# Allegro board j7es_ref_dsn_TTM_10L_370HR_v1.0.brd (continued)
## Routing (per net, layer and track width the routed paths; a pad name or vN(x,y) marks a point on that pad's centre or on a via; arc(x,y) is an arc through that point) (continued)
C_SGMII2_TX0_N: length 50.7
  TOP w0.122: U9.AF18 v1(95.85,80.95)
  L7-SIGNAL w0.099: v1(89.28,126.99) 89.48,126.79 arc(89.53,126.72) 89.56,126.63 arc(89.56,126.61) 89.56,126.59 89.56,126.14 arc(89.61,125.89) 89.75,125.69 92.36,123.07 arc(92.66,122.87) 93.02,122.8 93.05,122.8 arc(93.18,122.77) 93.29,122.7 93.48,122.51 arc(93.66,122.24) 93.73,121.92 93.73,118.68 arc(93.81,118.26) 94.05,117.9 94.85,117.09 arc(95.15,116.66) 95.25,116.14 95.25,100.87 arc(95.41,100.05) 95.88,99.35 96.33,98.9 arc(96.68,98.38) 96.8,97.77 96.8,84.36 arc(96.77,84.28) 96.72,84.22 96.69,84.18 96.68,84.18 arc(96.56,84.03) 96.52,83.84 arc(96.5,83.75) 96.45,83.67 96.34,83.56 arc(96.27,83.45) 96.24,83.31 96.24,81.68 arc(96.18,81.37) 96,81.1 v1(95.85,80.95)
  BOTTOM w0.188: C215.1 89.33,127.68 89.33,127.04 v1(89.28,126.99)
C_SGMII2_TX0_P: length 50.7
  TOP w0.122: U9.AG17 v1(96.65,81.75)
  L7-SIGNAL w0.099: v1(96.65,81.75) 96.65,81.5 arc(96.74,81.37) 96.9,81.4 96.96,81.45 arc(97.01,81.53) 97.03,81.63 97.03,83.4 97.02,83.41 arc(96.99,83.53) 96.92,83.64 96.9,83.66 arc(96.83,83.82) 96.9,83.98 96.9,83.99 arc(97.01,84.16) 97.05,84.36 97.05,97.77 arc(96.91,98.48) 96.51,99.08 96.06,99.53 arc(95.65,100.14) 95.5,100.87 95.5,100.87 95.5,116.14 arc(95.38,116.75) 95.03,117.27 94.23,118.08 arc(94.05,118.36) 93.98,118.68 93.98,121.92 arc(93.9,122.33) 93.66,122.69 93.47,122.88 arc(93.28,123.01) 93.05,123.05 93.02,123.05 arc(92.76,123.1) 92.54,123.25 89.93,125.87 arc(89.84,125.99) 89.81,126.14 89.81,126.64 arc(89.84,126.75) 89.9,126.84 v1(90.04,126.99)
  BOTTOM w0.188: C214.1 89.92,127.12 v1(90.04,126.99)
C_UART4_RXD: length 39.3
  TOP w0.191: U9.W23 v1(91.85,75.35)
  L9-SIGNAL w0.097: TPX41.1 55.75,74.41 59.69,74.41 61.34,76.06 74.85,76.06 76.5,74.41 84.96,74.41 85.47,74.92 91.42,74.92 v1(91.85,75.35)
C_UART4_TXD: length 41.1
  TOP w0.191: U9.W28 v1(87.85,75.35)
  L4-SIGNAL w0.097: v1(87.85,75.35) 87.48,75.72 86.96,75.72 85.75,76.93 68.73,76.93 67.67,77.99 49.63,77.99 TPX81.1
C_UB981_DOUT0_N: length 4.3
  BOTTOM w0.119: C3121.1 109.38,14.22 109.03,14.57 109.03,14.98 108.63,15.38 ; U3019.26 107.83,18.25 107.72,18.14 107.72,16.52 108.1,16.14
C_UB981_DOUT0_P: length 4.6
  BOTTOM w0.119: 107.84,16.03 107.46,16.41 107.46,18.11 107.34,18.23 U3019.27 ; 108.52,15.12 108.68,14.96 108.68,14.36 108.55,14.23 107.99,14.23 C3119.1
C_USB_SS_TX1_N: length 99.4
  TOP w0.157: U9.AF10 103.05,80.94 v1(103.05,80.95)
  L9-SIGNAL w0.114: v1(156.46,132.2) 156.63,132.03 arc(156.7,131.93) 156.72,131.83 156.72,131.61 arc(156.66,131.33) 156.5,131.09 151.97,126.56 arc(151.96,126.55) 151.95,126.54 arc(150.97,125.9) 149.82,125.67 149.82,125.67 116.31,125.67 116.21,125.66 116.19,125.66 arc(115.03,125.43) 114.05,124.77 114.03,124.77 103.5,114.24 arc(103.03,113.56) 102.85,112.75 arc(102.85,112.7) 102.84,112.65 102.86,112.64 102.86,98.49 102.87,98.49 arc(102.74,97.86) 102.39,97.33 100.44,95.38 99.95,94.2 99.95,88.33 99.95,88.32 99.76,87.7 99.76,82.56 arc(99.8,82.35) 99.91,82.18 100.1,81.99 arc(100.2,81.86) 100.23,81.69 arc(100.25,81.58) 100.31,81.49 arc(100.44,81.41) 100.59,81.38 102.58,81.38 arc(102.62,81.37) 102.66,81.34 v1(103.05,80.95)
  BOTTOM w0.16: C219.1 v1(156.46,132.2)
C_USB_SS_TX1_P: length 99.4
  TOP w0.157: v1(103.85,81.75) 103.45,81.35 U9.AG9
  L9-SIGNAL w0.114: v1(103.85,81.75) 103.69,81.91 arc(103.45,82.07) 103.16,82.13 100.48,82.13 arc(100.32,82.16) 100.18,82.25 100.12,82.32 arc(100.03,82.45) 100,82.6 100,84.56 100.01,84.57 100.01,87.61 100.18,88.23 100.19,88.3 100.19,94.15 100.64,95.24 102.56,97.16 arc(102.96,97.77) 103.11,98.49 103.11,112.73 103.1,112.74 arc(103.27,113.45) 103.68,114.06 114.22,124.6 arc(115.12,125.2) 116.19,125.42 116.31,125.42 149.76,125.42 arc(149.79,125.42) 149.82,125.42 arc(151.07,125.66) 152.13,126.36 arc(152.14,126.37) 152.16,126.39 156.68,130.91 arc(156.9,131.23) 156.97,131.61 156.97,131.77 arc(157,131.93) 157.09,132.07 v1(157.23,132.2)
  BOTTOM w0.16: C218.1 v1(157.23,132.2)
C_USB_SS_TX2_N: length 126.6
  TOP w0.157: U9.AF9 103.85,80.94 v1(103.85,80.95)
  L7-SIGNAL w0.097: v1(103.85,80.95) 103.67,81.13 arc(103.53,81.34) 103.49,81.58 103.49,83.4 arc(103.52,83.55) 103.61,83.68 103.75,83.83 arc(103.87,84.01) 103.92,84.22 103.92,87.43 arc(103.98,87.75) 104.16,88.02 arc(104.22,88.11) 104.24,88.22 104.24,108.66 arc(104.19,108.9) 104.06,109.1 103.98,109.18 arc(103.86,109.36) 103.81,109.59 103.81,115.67 arc(104.07,116.97) 104.81,118.07 109.79,123.05 arc(111.45,124.16) 113.4,124.55 152.22,124.55 arc(153.41,124.31) 154.42,123.63 155.53,122.53 arc(156.53,121.86) 157.71,121.63 174.99,121.63 arc(175.98,121.82) 176.81,122.38 180.95,126.52 arc(181.22,126.93) 181.32,127.41 181.32,131.64 arc(181.28,131.84) 181.17,132 v1(181.1,132.07)
  BOTTOM w0.16: C217.1 181.1,132.61 181.26,132.45 181.26,132.23 v1(181.1,132.07)
C_USB_SS_TX2_P: length 126.6
  TOP w0.157: v1(104.65,81.75) 104.65,81.74 U9.AG8
  L7-SIGNAL w0.097: v1(181.86,132.07) 181.69,131.9 arc(181.62,131.79) 181.59,131.66 181.59,127.41 arc(181.48,126.82) 181.15,126.33 177,122.18 arc(176.08,121.57) 174.99,121.35 157.71,121.35 arc(156.42,121.61) 155.33,122.34 154.23,123.44 arc(153.31,124.06) 152.22,124.27 113.4,124.27 arc(111.55,123.9) 109.98,122.86 105,117.87 arc(104.33,116.86) 104.09,115.67 104.09,109.59 arc(104.11,109.47) 104.18,109.37 104.25,109.3 arc(104.45,109) 104.52,108.66 104.52,88.22 arc(104.47,88.01) 104.35,87.83 arc(104.23,87.65) 104.19,87.43 104.19,84.27 104.24,83.58 104.24,82.38 104.24,81.59 arc(104.27,81.48) 104.33,81.39 arc(104.53,81.35) 104.65,81.53 v1(104.65,81.75)
  BOTTOM w0.16: C216.1 181.86,132.61 181.71,132.45 181.71,132.23 v1(181.86,132.07)
CAN_WAKE: length 30.8
  BOTTOM w0.127: R2101.2 v2(34.92,30.98) ; v2(34.92,30.98) 30.99,34.91 27.56,34.91 26.09,33.44 JZ2000.10 ; v2(34.92,30.98) 35.43,30.98 36.45,31.99 RJ2008.2
CAN_WKUP: length 8.8
  TOP w0.229: v1(136.09,96.33) 135.91,96.15 U27.47
  L7-SIGNAL w0.097: TPX299.1 143.12,96.38 142.76,96.02 139.34,96.02 139.06,95.75 136.68,95.75 v1(136.09,96.33)
CANH_1: length 46.1
  TOP w0.127: U2007.13 40,28.18 38.48,26.66 31.88,26.66 29.11,29.43 JZ2000.4
  BOTTOM w0.127: R2098.1 25.4,29.33 JZ2000.4
CANL_1: length 45.1
  TOP w0.127: U2007.12 38.73,28.18 37.85,27.29 32.38,27.29 28.32,31.36 25.37,31.36 JZ2000.3
  BOTTOM w0.127: JZ2000.3 25.48,31.61 27.56,31.61
CLK2X_B: length 5.8
  TOP w0.127: v2(194.22,104) 195.58,105.36 R1032.2
  TOP w0.203: v2(194.22,104) 194.18,104 193.78,103.6 U1007.1
  BOTTOM w0.203: R1146.1 v2(194.22,104)
CLKGEN_USB_REFCLK_N: length 44.7
  TOP w0.122: v1(103.85,80.15) 103.45,79.75 U9.AE9
  L4-SIGNAL w0.099: v1(103.85,80.15) 103.85,80.13 arc(103.76,79.95) 103.55,79.93 arc(103.46,80.01) 103.42,80.13 103.42,83.55 arc(103.38,83.76) 103.27,83.93 102.92,84.27 arc(102.87,84.35) 102.85,84.45 102.85,87.57 arc(102.95,88.09) 103.24,88.52 103.24,88.53 arc(103.49,88.9) 103.58,89.34 103.58,92.55 arc(103.5,92.97) 103.26,93.33 102.94,93.65 arc(102.79,93.87) 102.74,94.12 102.74,101.66 arc(102.6,102.4) 102.18,103.02 101.02,104.18 arc(100.7,104.66) 100.58,105.23 100.58,112.82 arc(100.85,114.15) 101.6,115.29 102.88,116.56 arc(103.34,117.25) 103.5,118.07 103.5,120.52 arc(103.52,120.61) 103.57,120.68 103.59,120.7 arc(103.66,120.75) 103.75,120.77 TPX429.1
CLKGEN_USB_REFCLK_P: length 44.7
  TOP w0.122: v1(103.05,79.35) 102.65,78.95 U9.AD10
  L4-SIGNAL w0.099: v1(103.05,79.35) 102.88,79.52 arc(102.72,79.76) 102.67,80.04 102.67,83.94 102.59,84.29 102.59,87.57 arc(102.71,88.18) 103.06,88.7 103.06,88.7 103.06,88.7 arc(103.26,89) 103.33,89.34 103.33,92.55 arc(103.26,92.88) 103.08,93.15 102.76,93.47 arc(102.56,93.77) 102.49,94.12 102.49,101.66 arc(102.36,102.3) 102,102.84 100.84,104 arc(100.46,104.57) 100.33,105.23 100.33,112.82 arc(100.61,114.25) 101.42,115.46 102.7,116.74 arc(103.11,117.35) 103.25,118.07 103.25,120.49 arc(103.23,120.61) 103.16,120.7 103.14,120.73 arc(103.1,120.76) 103.05,120.77 TPX428.1
CON_DP0_AUX_N: length 11.4
  TOP w0.119: 129.14,20.1 129.54,20.5 129.54,21.2 129.26,21.48 FL3015.3 ; 129.14,20.1 129.52,19.72 129.52,17.37 arc(129.51,17.32) 129.48,17.28 D3029.1 129.41,16.79 arc(129.5,16.75) 129.54,16.66 129.54,16.36 arc(129.74,15.87) 130.24,15.67 131.44,15.67 arc(131.55,15.63) 131.59,15.53 131.59,15.2 arc(131.55,15.11) 131.47,15.08 131.34,15.08 arc(131.25,15.04) 131.22,14.96 J3003.17 ; 129.14,20.1 R3061.1
CON_DP0_AUX_P: length 11.4
  TOP w0.119: R3062.2 130.19,20.1 ; 130.19,20.1 129.8,20.49 129.8,21.21 130.07,21.48 FL3015.2 ; 130.19,20.1 129.78,19.68 129.78,17.41 129.79,17.4 arc(129.8,17.34) 129.84,17.3 D3030.1 129.92,16.79 arc(129.85,16.76) 129.8,16.7 arc(129.8,16.68) 129.8,16.66 129.8,16.36 arc(129.93,16.06) 130.24,15.93 131.44,15.93 arc(131.73,15.81) 131.85,15.53 131.85,15.2 arc(131.88,15.11) 131.97,15.08 132.1,15.08 arc(132.18,15.04) 132.22,14.96 J3003.15
CON_DP0_TX0_N: length 8.6
  TOP w0.119: FL3024.3 141.18,18.2 141.45,17.92 141.45,17.48 140.91,16.93 D3033.1 141.33,16.79 arc(141.42,16.75) 141.45,16.67 141.45,15.98 arc(141.37,15.78) 141.17,15.7 138.97,15.7 arc(138.7,15.58) 138.59,15.32 138.59,15.2 arc(138.55,15.11) 138.47,15.08 138.34,15.08 arc(138.25,15.04) 138.22,14.96 J3003.3
CON_DP0_TX0_P: length 8.6
  TOP w0.119: FL3024.2 141.99,18.16 141.71,17.88 141.71,17.42 142.26,16.88 D3034.1 141.83,16.79 arc(141.75,16.75) 141.72,16.67 141.72,15.98 arc(141.56,15.59) 141.17,15.43 138.97,15.43 arc(138.88,15.4) 138.85,15.32 138.85,15.2 arc(138.88,15.11) 138.97,15.08 139.1,15.08 arc(139.18,15.04) 139.22,14.96 J3003.1
CON_DP0_TX1_N: length 8.2
  TOP w0.119: FL3020.3 138.26,19.85 138.54,19.57 138.54,19.08 137.99,18.53 D3021.1 138.41,18.44 arc(138.5,18.41) 138.53,18.32 138.53,17.32 arc(138.5,17.16) 138.41,17.02 137.22,15.83 arc(137.12,15.68) 137.09,15.5 137.09,15.2 arc(137.05,15.11) 136.97,15.08 136.84,15.08 arc(136.75,15.04) 136.72,14.96 J3003.6
CON_DP0_TX1_P: length 8.2
  TOP w0.119: FL3020.2 139.07,19.81 138.8,19.54 138.8,19.07 139.34,18.53 D3022.1 138.91,18.44 arc(138.83,18.41) 138.79,18.32 138.79,17.32 arc(138.74,17.06) 138.59,16.83 137.41,15.65 arc(137.36,15.58) 137.35,15.5 137.35,15.2 arc(137.38,15.11) 137.47,15.08 137.6,15.08 arc(137.68,15.04) 137.72,14.96 J3003.4
CON_DP0_TX2_N: length 5.9
  TOP w0.119: FL3023.3 135.34,18.2 135.62,17.91 135.62,17.43 135.07,16.88 D3031.1 135.28,16.79 arc(135.5,16.7) 135.59,16.48 135.59,15.35 arc(135.55,15.25) 135.45,15.21 arc(135.28,15.14) 135.22,14.98 J3003.9
CON_DP0_TX2_P: length 5.9
  TOP w0.119: J3003.7 136.22,14.98 arc(136.19,15.11) 136.12,15.21 135.91,15.42 arc(135.88,15.47) 135.87,15.52 135.85,15.53 135.85,16.56 arc(135.92,16.72) 136.08,16.79 D3032.1 136.42,16.9 135.88,17.43 135.88,17.89 136.15,18.16 FL3023.2
CON_DP0_TX3_N: length 8.7
  TOP w0.119: FL3019.3 132.29,20.14 132.29,19.85 132.57,19.56 132.57,19.09 132.02,18.53 132.02,18.44 D3019.1 132.42,18.44 arc(132.53,18.4) 132.57,18.29 132.57,16.54 arc(132.75,16.11) 133.19,15.93 133.66,15.93 arc(133.96,15.8) 134.09,15.5 134.09,15.19 arc(134.02,15.1) 133.92,15.06 arc(133.78,15.01) 133.72,14.86 J3003.12
CON_DP0_TX3_P: length 8.7
  TOP w0.119: 133.37,18.44 133.03,18.44 arc(132.91,18.41) 132.83,18.31 arc(132.83,18.3) 132.83,18.29 132.83,16.54 arc(132.94,16.29) 133.19,16.19 133.66,16.19 arc(134.15,15.99) 134.35,15.5 134.35,15.17 arc(134.38,15.1) 134.45,15.07 134.5,15.07 arc(134.65,15.01) 134.72,14.85 J3003.10 ; 133.37,18.44 D3020.1 ; 133.37,18.44 133.37,18.55 132.83,19.08 132.83,19.54 133.1,19.81 133.1,20.14 FL3019.2
CONN_USB1_DM: length 22.7
  TOP w0.122: FL1001.2 173.2,138.85 173.46,139.11 173.46,142.37 171.62,144.2 171.62,147.48 172.87,148.73 177.75,148.73 180.87,145.61 180.87,144.72 J1000.2
CONN_USB1_DP: length 22.7
  TOP w0.122: FL1001.3 174.02,138.85 173.74,139.13 173.74,142.48 171.9,144.32 171.9,147.37 172.99,148.45 177.63,148.45 180.59,145.49 180.59,144.47 180.38,144.25 J1000.3
CONN_USB2_DM: length 10.4
  TOP w0.16: J1001.2 156.7,142.47 156.2,141.96 156.2,141.74 156.84,141.09 159.13,141.09 160.53,139.69 160.53,137.91 160.81,137.63 FL1000.3
CONN_USB2_DP: length 10.8
  TOP w0.16: J1001.3 154.7,142.67 155.52,141.85 155.78,141.85 155.89,141.74 155.89,141.61 156.72,140.78 159,140.78 160.22,139.56 160.22,137.86 159.99,137.63 FL1000.2
CONN_USB_RXN0: length 8.5
  BOTTOM w0.16: J1000.5 177.19,141.9 177.19,141.55 177.57,141.16 178.98,141.16 179.56,140.58 179.56,140.36 179.47,140.26 U1000.6 U1000.5 179.47,137.29 179.32,137.14 179.32,137.13 179.04,136.86 FL1002.3
CONN_USB_RXN1: length 8.5
  BOTTOM w0.16: J1001.5 152.55,141.9 152.55,141.55 152.94,141.16 154.35,141.16 154.93,140.58 154.93,140.36 154.83,140.26 U3021.6 U3021.5 154.83,137.29 154.68,137.14 154.68,137.13 154.41,136.86 FL3028.3
CONN_USB_RXP0: length 8.5
  BOTTOM w0.16: J1000.6 177.49,141.9 177.49,141.68 177.7,141.47 179.11,141.47 179.87,140.71 179.87,140.36 179.97,140.26 U1000.7 U1000.4 179.97,138.12 179.77,137.92 179.77,137.36 179.86,137.27 FL1002.2
CONN_USB_RXP1: length 8.5
  BOTTOM w0.16: J1001.6 152.85,141.9 152.85,141.68 153.06,141.47 154.47,141.47 155.23,140.71 155.23,140.36 155.33,140.26 U3021.7 U3021.4 155.33,138.12 155.13,137.92 155.13,137.36 155.22,137.27 FL3028.2
CONN_USB_TXN0: length 8.2
  BOTTOM w0.16: FL1003.3 181.08,138.01 180.97,138.12 U1000.2 U1000.9 180.97,140.32 181.05,140.4 181.05,140.78 181.74,141.47 182.98,141.47 183.19,141.68 183.19,141.9 J1000.8
CONN_USB_TXN1: length 8.2
  BOTTOM w0.16: J1001.8 158.55,141.9 158.55,141.68 158.34,141.47 157.1,141.47 156.41,140.78 156.41,140.4 156.33,140.32 U3021.9 U3021.2 156.33,138.12 156.44,138.01 FL3029.3
CONN_USB_TXP0: length 8.3
  BOTTOM w0.16: J1000.9 183.49,141.9 183.49,141.55 183.11,141.16 181.86,141.16 181.36,140.66 181.36,140.4 181.47,140.29 U1000.10 U1000.1 181.47,137.55 181.89,137.12 FL1003.2
CONN_USB_TXP1: length 8.3
  BOTTOM w0.16: FL3029.2 157.25,137.12 156.83,137.55 U3021.1 U3021.10 156.83,140.29 156.72,140.4 156.72,140.66 157.23,141.16 158.47,141.16 158.85,141.55 158.85,141.9 J1001.9
CS_P: length 24.5
  TOP w0.203: R1031.2 v2(183.39,57.01)
  L2-SIGNAL w0.305: v2(174.37,70.47) 174.37,69.33 174.75,68.95 175.26,68.95 176.28,67.93 176.28,65.65 181.23,60.7 184.53,60.7 185.55,59.68 185.55,58.28 184.78,57.52 183.9,57.52 v2(183.39,57.01)
  BOTTOM w0.305: C1200.1 178.31,71.62 v2(177.55,70.86)
  vias: v2(172.21,70.86) v2(173.35,70.86) v2(176.4,70.86)
CSI0_RX0_N: length 60.8
  TOP w0.119: U9.B19 95.45,61.35 v1(95.05,60.95)
  L2-SIGNAL w0.099: v1(95.05,60.95) 94.68,60.58 94.68,58.94 96.39,57.23 96.39,48.63 95.5,47.74 95.5,43.8 92.13,40.43 89.71,40.43 84.71,35.42 64.64,35.42 64.13,35.93 v1(64.13,36.44)
  BOTTOM w0.119: v1(64.13,36.44) 64.13,36.08 64.39,35.83 64.39,30.86 64.27,30.74 U3022.24
CSI0_RX0_P: length 60.8
  TOP w0.119: U9.A20 94.65,60.54 v1(94.25,60.14)
  L2-SIGNAL w0.099: v1(94.25,60.14) 94.35,60.04 94.35,58.8 95.16,57.99 95.16,57.85 94.8,57.49 94.8,57.35 94.91,57.24 95.05,57.24 95.41,57.6 95.55,57.6 96.06,57.09 96.06,56.86 95.96,56.76 95.73,56.76 95.63,56.67 95.63,56.51 95.73,56.41 95.96,56.41 96.06,56.31 96.06,48.77 95.17,47.88 95.17,43.94 91.99,40.76 89.58,40.76 84.57,35.75 64.78,35.75 64.57,35.97 64.57,36.23 64.77,36.44 v1(64.9,36.44)
  BOTTOM w0.119: U3022.25 64.77,30.74 64.65,30.86 64.65,35.83 64.9,36.08 v1(64.9,36.44)
CSI0_RX1_N: length 62.2
  TOP w0.119: U9.D18 96.25,62.95 v1(95.85,62.55)
  L2-SIGNAL w0.099: v1(65.13,35.04) 65.13,34.44 65.65,33.92 84.73,33.92 90.42,39.61 92.71,39.61 97.41,44.31 97.41,57.65 96.34,58.71 96.34,59.83 96.27,59.91 96.27,61.05 96,61.31 95.7,61.31 95.48,61.53 95.48,62.18 v1(95.85,62.55)
  BOTTOM w0.119: U3022.26 65.27,30.74 65.39,30.86 65.39,34.43 65.13,34.68 v1(65.13,35.04)
CSI0_RX1_P: length 62.2
  TOP w0.119: U9.C19 95.45,62.15 v1(95.05,61.75)
  L2-SIGNAL w0.099: v1(95.05,61.75) 94.95,61.64 94.95,61.43 95.07,61.31 95.2,61.31 95.42,61.1 95.42,59.88 95.52,59.78 95.89,59.78 96.01,59.65 96.01,59.46 95.91,59.36 95.24,59.36 95.14,59.26 95.14,59.11 95.25,59 95.89,59 95.99,58.9 95.99,58.6 97.08,57.51 97.08,44.45 92.57,39.94 90.29,39.94 84.6,34.25 65.79,34.25 65.52,34.52 65.52,34.93 65.63,35.04 v1(65.9,35.04)
  BOTTOM w0.119: U3022.27 65.77,30.74 65.65,30.86 65.65,34.43 65.9,34.68 v1(65.9,35.04)
CSI0_RX2_N: length 62.6
  TOP w0.119: U9.D17 96.65,62.55 v1(96.65,62.55)
  L2-SIGNAL w0.099: v1(66.13,33.52) 66.13,32.97 66.61,32.5 84.84,32.5 90.81,38.47 95.25,38.47 95.88,39.11 95.88,40.12 98.55,42.79 98.55,57.9 97.82,58.64 97.82,61.12 97.55,61.38 97.3,61.38 97.08,61.59 97.08,61.83 96.65,62.26 v1(96.65,62.55)
  BOTTOM w0.119: U3022.28 66.27,30.74 66.39,30.86 66.39,32.91 66.13,33.16 v1(66.13,33.52)
CSI0_RX2_P: length 62.7
  TOP w0.119: v1(95.85,61.75) 96.25,62.15 U9.C18
  L2-SIGNAL w0.099: v1(66.9,33.52) 66.67,33.52 66.55,33.39 66.55,33.03 66.74,32.83 84.7,32.83 90.67,38.8 95.11,38.8 95.55,39.24 95.55,40.26 98.22,42.93 98.22,57.76 97.49,58.5 97.49,58.82 97.25,59.05 96.87,59.05 96.77,59.15 96.77,59.31 96.87,59.4 97.39,59.4 97.49,59.5 97.49,59.73 97.44,59.78 97.18,59.78 97.02,59.95 97.02,61.19 96.9,61.31 96.56,61.31 96.13,61.75 v1(95.85,61.75)
  BOTTOM w0.119: v1(66.9,33.52) 66.9,33.16 66.65,32.91 66.65,30.86 66.77,30.74 U3022.29
CSI0_RX3_N: length 63.6
  TOP w0.119: v1(97.45,63.35) 97.45,63.35 U9.E16
  L2-SIGNAL w0.099: v1(67.13,32.07) 67.13,31.53 67.69,30.98 84.71,30.98 91.19,37.45 96.27,37.45 97.76,38.95 97.76,40.35 99.69,42.28 99.69,58.28 99.06,58.92 99.06,61.16 98.62,61.61 98.62,61.9 98.4,62.11 98.07,62.11 97.82,62.37 97.82,62.7 97.6,62.91 97.55,62.91 97.36,63.1 97.36,63.25 v1(97.45,63.35)
  BOTTOM w0.119: U3022.30 67.27,30.74 67.39,30.86 67.39,31.46 67.13,31.71 v1(67.13,32.07)
CSI0_RX3_P: length 63.6
  TOP w0.119: v1(96.65,63.35) 97.05,63.75 U9.E17
  L2-SIGNAL w0.099: v1(67.9,32.07) 67.65,32.07 67.55,31.97 67.55,31.59 67.83,31.31 84.57,31.31 91.05,37.79 96.13,37.79 97.43,39.09 97.43,40.49 99.36,42.42 99.36,58.15 98.73,58.78 98.73,59.1 98.63,59.2 98.4,59.2 98.3,59.3 98.3,59.45 98.4,59.55 98.63,59.55 98.73,59.65 98.73,61.03 98.38,61.38 98.1,61.38 97.88,61.59 97.88,61.83 97.54,62.18 97.3,62.18 97.08,62.39 97.08,62.91 v1(96.65,63.35)
  BOTTOM w0.119: v1(67.9,32.07) 67.9,31.71 67.65,31.46 67.65,30.86 67.77,30.74 U3022.31
CSI0_RXCLK_N: length 59.2
  TOP w0.119: v1(94.25,60.95) 94.65,61.35 U9.B20
  L2-SIGNAL w0.099: v1(94.25,60.95) 93.88,60.58 93.88,58.61 93.73,58.46 93.73,49.52 91.57,47.36 91.57,42.53 90.35,41.31 89.21,41.31 84.85,36.95 63.5,36.95 63.14,37.31 v1(63.14,37.84)
  BOTTOM w0.119: U3022.22 63.27,30.74 63.39,30.86 63.39,37.23 63.14,37.48 v1(63.14,37.84)
CSI0_RXCLK_P: length 57.3
  TOP w0.119: U9.A21 93.45,60.14 v1(93.45,60.14)
  L2-SIGNAL w0.099: v1(63.9,37.84) 63.73,37.84 63.54,37.65 63.54,37.38 63.64,37.28 84.71,37.28 89.08,41.64 90.21,41.64 91.24,42.67 91.24,47.5 93.4,49.66 93.4,60.09 v1(93.45,60.14)
  BOTTOM w0.119: v1(63.9,37.84) 63.9,37.48 63.65,37.23 63.65,30.86 63.77,30.74 U3022.23
CSI0_RXRCALIB: length 3
  TOP w0.229: U9.F16 97.45,64.15 v1(97.45,64.15)
  BOTTOM w0.114: v1(97.45,64.15) 97.85,63.75 97.85,63.18 98.08,62.95 R238.1
CSI1_RX0_N: length 23.2
  TOP w0.119: v1(97.45,60.95) 97.85,61.35 U9.B16
  L5-PWR/GND w0.076: TPX327.1 95.12,39.86 94.91,40.07 94.91,40.18 95.11,40.38 95.11,47.57 97.08,49.54 97.08,60.57 v1(97.45,60.95)
CSI1_RX0_P: length 22.3
  TOP w0.119: v1(96.65,60.14) 97.05,60.54 U9.A17
  L5-PWR/GND w0.076: v1(96.65,60.14) 96.88,59.92 96.88,49.62 94.91,47.65 94.91,40.47 94.7,40.26 94.7,40.07 94.49,39.86 TPX328.1
CSI1_RX1_N: length 25.4
  TOP w0.119: U9.D15 98.65,62.95 v1(98.25,62.55)
  L5-PWR/GND w0.076: TPX239.1 97.03,39.86 96.81,40.07 96.81,40.89 98.3,42.37 98.3,59.73 98.36,59.79 98.4,59.79 98.61,60 98.61,60.29 98.4,60.5 98.4,60.59 98.61,60.8 98.61,61.09 98.4,61.3 97.99,61.3 97.81,61.48 97.81,61.89 97.79,61.91 97.79,62.09 v1(98.25,62.55)
CSI1_RX1_P: length 24
  TOP w0.119: v1(97.45,61.75) 97.85,62.15 U9.C16
  L5-PWR/GND w0.076: TPX240.1 96.39,39.86 96.61,40.07 96.61,40.97 98.09,42.46 98.09,59.74 97.89,59.94 97.89,60.29 98.1,60.5 98.1,60.59 97.89,60.8 97.89,61.11 97.45,61.55 v1(97.45,61.75)
CSI1_RX2_N: length 24.3
  TOP w0.119: U9.D14 99.45,62.95 v1(99.85,62.55)
  L5-PWR/GND w0.076: v1(99.85,62.55) 99.21,62.22 99.18,62.12 99.21,62.06 99.21,40.75 98.72,40.25 98.72,40.07 98.93,39.86 TPX368.1
CSI1_RX2_P: length 24.2
  TOP w0.119: U9.C15 98.65,62.15 v1(98.25,61.75)
  L5-PWR/GND w0.076: TPX369.1 98.3,39.86 98.51,40.07 98.51,40.34 99.01,40.83 99.01,62.01 98.99,62.03 98.89,62.07 v1(98.25,61.75)
CSI1_RX3_N: length 25
  TOP w0.119: U9.E13 v1(100.65,63.35)
  L2-SIGNAL w0.076: TPX283.1 100.84,39.86 100.53,40.16 100.53,58.62 100.03,59.13 100.03,59.76 100.21,59.94 100.21,60.06 100.22,60.07 100.22,62.91 v1(100.65,63.35)
CSI1_RX3_P: length 25
  TOP w0.119: U9.E14 v1(99.85,63.35)
  L2-SIGNAL w0.076: TPX284.1 100.2,39.86 100.33,39.98 100.33,58.54 99.82,59.05 99.82,59.65 99.48,59.98 99.48,62.98 v1(99.85,63.35)
CSI1_RXCLK_N: length 37.2
  TOP w0.119: v1(96.65,60.95) 97.05,61.35 U9.B17
  L5-PWR/GND w0.076: v1(96.65,60.95) 96.29,60.59 96.29,59.58 96.01,59.3 96.01,51.01 94.11,49.11 94.11,42.88 84.3,33.08 84.3,29.86 TPX347.1
CSI1_RXCLK_P: length 36.3
  TOP w0.119: v1(95.85,60.14) 96.25,60.54 U9.A18
  L5-PWR/GND w0.076: TPX348.1 84.1,29.86 84.1,33.16 93.9,42.97 93.9,49.19 95.81,51.09 95.81,59.38 96.09,59.66 96.09,59.9 v1(95.85,60.14)
CSI1_RXRCALIB: length 1.5
  TOP w0.229: v1(98.25,64.15) 98.65,64.55 U9.F15
  BOTTOM w0.229: R234.1 98.51,63.89 v1(98.25,64.15)
CSI2_EXP_A_GPIO2: length 49.5
  TOP w0.229: U9.T27 89.05,72.55 v1(88.65,72.15)
  BOTTOM w0.127: v1(88.65,72.15) 88.03,72.76 81.03,72.76 80.01,71.74 72.14,71.74 69.72,74.16 43.56,74.16 43.18,73.78 42.42,73.78 TPX138.1
CSI2_EXP_A_GPIO4: length 32
  TOP w0.229: v1(91.05,72.15) 91.45,72.55 U9.T24
  L9-SIGNAL w0.097: TPX16.1 81.92,69.33 83.76,71.17 86.12,71.17 86.67,71.72 86.68,71.72 87.41,71.72 87.41,71.72 88.22,71.72 88.23,71.72 90.62,71.72 v1(91.05,72.15)
DDR0_CAL0: length 0.6
  TOP w0.191: U9.H2 v1(109.45,65.75)
DP0_AUX_N: length 1.5
  TOP w0.119: FL3015.4 129.26,23.71 129.54,23.99 129.54,24.48 C415.2
DP0_AUX_P: length 1.5
  TOP w0.119: FL3015.1 130.07,23.71 129.8,23.99 129.8,24.48 C414.2
DP0_CONFIG1: length 4.1
  TOP w0.229: v1(133.49,11.2) 133.22,11.48 J3003.13
  BOTTOM w0.229: R3118.1 v1(133.49,11.2)
DP0_CONFIG2: length 2.8
  TOP w0.229: J3003.14 v1(132.72,11.86)
  BOTTOM w0.229: R3119.1 132.35,12.23 v1(132.72,11.86)
DP0_HPD: length 3.4
  TOP w0.229: v1(130.98,11.49) 130.95,11.49 130.72,11.72 J3003.18
  BOTTOM w0.229: v1(130.98,11.49) 130.98,11.95 130.91,12.02 R3121.2
DP0_HPD/PRG1_IEP0_EDIO_OUTVALID: length 54.8
  TOP w0.191: U9.Y4 107.85,76.14 v1(107.85,76.15)
  L9-SIGNAL w0.097: TPX205.1 156.72,75.68 141.73,75.68 136.4,81.02 131.19,81.02 130.94,81.27 123.19,81.27 122.3,80.38 116.59,80.38 112.78,76.57 110.46,76.57 110.41,76.52 108.22,76.52 v1(107.85,76.15)
DP0_TX0_N: length 1.5
  TOP w0.119: 141.2,20.17 141.2,20.41 141.47,20.69 141.47,21.18 C422.2 ; 141.2,20.17 FL3024.4 ; 141.2,20.17 141.2,20.15
DP0_TX0_P: length 1.5
  TOP w0.119: C423.2 141.74,21.18 141.74,20.69 142.01,20.41 142.01,20.17 ; 142.01,20.15 142.01,20.17 ; 142.01,20.17 FL3024.1
DP0_TX1_N: length 1.5
  TOP w0.119: 138.28,21.82 138.28,22.06 138.55,22.34 138.55,22.83 C420.2 ; 138.28,21.82 FL3020.4 ; 138.28,21.82 138.28,21.8
DP0_TX1_P: length 1.5
  TOP w0.119: FL3020.1 139.09,21.82 ; 139.09,21.82 139.09,22.06 138.81,22.34 138.81,22.83 C421.2 ; 139.09,21.82 139.09,21.8
DP0_TX2_N: length 1.5
  TOP w0.119: 135.36,20.17 135.36,20.41 135.63,20.69 135.63,21.18 C418.2 ; 135.36,20.17 FL3023.4 ; 135.36,20.17 135.36,20.15
DP0_TX2_P: length 1.5
  TOP w0.119: C419.2 135.89,21.18 135.89,20.69 136.17,20.41 136.17,20.17 ; 136.17,20.17 FL3023.1 ; 136.17,20.17 136.17,20.15
DP0_TX3_N: length 1.4
  TOP w0.119: C416.2 132.58,22.7 132.58,22.21 132.31,21.94 FL3019.4
DP0_TX3_P: length 1.4
  TOP w0.119: C417.2 132.85,22.7 132.85,22.21 133.12,21.94 FL3019.1
DSI0_TX0_N: length 41
  TOP w0.119: U9.D11 101.85,62.95 v1(102.25,62.55)
  L7-SIGNAL w0.076: v1(108.46,31.61) 108.76,31.92 109.05,31.92 109.6,32.47 109.6,37.07 104.09,42.59 104.09,48.21 103.2,49.1 103.2,59.78 103.2,59.79 103.41,60 103.41,60.29 103.2,60.5 103.2,60.59 103.41,60.8 103.41,61.09 103.2,61.3 102.84,61.3 102.61,61.53 102.61,61.89 102.4,62.1 102.04,62.1 101.98,62.16 101.98,62.27 v1(102.25,62.55)
  BOTTOM w0.119: v1(108.46,31.61) 108.46,31.79 108.6,31.93 108.77,31.93 108.95,31.75 108.95,28.44 108.83,28.32 U3019.57
DSI0_TX0_P: length 40.5
  TOP w0.119: U9.C12 v1(101.45,61.75)
  L7-SIGNAL w0.076: v1(101.45,61.75) 101.73,62.02 101.83,62.02 101.9,61.96 101.9,61.6 102.11,61.39 102.46,61.39 102.7,61.16 102.7,60.8 102.91,60.59 102.91,60.5 102.7,60.29 102.7,60 102.91,59.79 102.99,59.79 103,59.78 103,59.7 103,49.01 103.89,48.12 103.89,42.5 109.4,36.99 109.4,32.55 108.97,32.12 108.71,32.12 v1(108.46,32.37)
  BOTTOM w0.119: U3019.58 109.34,28.32 109.22,28.44 109.22,31.86 108.88,32.19 108.61,32.19 108.5,32.31 108.5,32.37 108.49,32.37 v1(108.46,32.37)
DSI0_TX1_N: length 40.8
  TOP w0.119: v1(101.45,62.55) 101.05,62.95 U9.D12
  L7-SIGNAL w0.076: v1(106.68,31.23) 106.96,31.51 107.18,31.51 107.57,31.9 107.57,37.45 102.96,42.06 102.96,47.69 101.42,49.22 101.42,59.38 101.9,59.85 101.9,60.44 101.67,60.66 101.81,60.8 101.81,61.09 101.6,61.3 101.27,61.3 101.24,61.3 101.21,61.32 101.21,61.34 101.05,61.5 101.05,62.04 101.18,62.16 101.18,62.27 v1(101.45,62.55)
  BOTTOM w0.119: U3019.55 107.83,28.32 107.95,28.44 107.95,30.85 107.25,31.55 106.97,31.55 106.68,31.26 v1(106.68,31.23)
DSI0_TX1_P: length 39.3
  TOP w0.119: U9.C13 100.25,62.15 v1(100.65,61.75)
  L7-SIGNAL w0.076: v1(100.65,61.75) 100.65,61.64 100.8,61.5 100.8,61.39 101.1,61.09 101.1,60.8 101.01,60.71 101.01,59.85 101.25,59.61 101.25,59.5 101.22,59.46 101.22,49.14 102.76,47.6 102.76,41.98 107.37,37.37 107.37,31.98 107.1,31.71 106.96,31.71 v1(106.68,31.99)
  BOTTOM w0.119: U3019.56 108.34,28.32 108.22,28.44 108.22,30.95 107.36,31.81 106.87,31.81 v1(106.68,31.99)
DSI0_TX2_N: length 37.5
  TOP w0.119: U9.B13 100.25,61.35 v1(100.65,60.95)
  L7-SIGNAL w0.076: v1(105.54,32.12) 105.82,32.4 105.95,32.4 106.01,32.41 106.38,32.77 106.38,36.52 100.28,42.62 100.28,60.57 v1(100.65,60.95)
  BOTTOM w0.119: U3019.53 106.83,28.32 106.95,28.44 106.95,29.81 105.54,31.23 105.54,32.12 v1(105.54,32.12)
DSI0_TX2_P: length 37.3
  TOP w0.119: U9.A14 v1(99.85,60.14)
  L7-SIGNAL w0.076: v1(105.54,32.88) 105.82,32.61 105.92,32.61 106.17,32.86 106.17,36.44 100.08,42.53 100.08,59.94 99.97,60.05 99.87,60.14 v1(99.85,60.14)
  BOTTOM w0.119: U3019.54 107.34,28.32 107.22,28.44 107.22,29.92 105.8,31.34 105.8,31.79 105.96,31.95 105.96,32.06 105.97,32.06 105.97,32.45 v1(105.54,32.88)
DSI0_TX3_N: length 38
  TOP w0.119: v1(99.85,60.95) 99.45,61.35 U9.B14
  L7-SIGNAL w0.076: v1(99.85,60.95) 99.66,60.95 arc(99.24,60.77) 99.06,60.35 99.06,52.02 arc(99.07,51.99) 99.08,51.96 99.09,51.96 arc(99.15,51.87) 99.16,51.77 99.16,42.21 104.88,36.49 104.88,32.03 106.63,30.28 106.63,29.75 106.38,29.5 106.1,29.5 v1(105.79,29.2)
  BOTTOM w0.119: U3019.51 105.83,28.32 105.95,28.44 105.95,29.04 v1(105.79,29.2)
DSI0_TX3_P: length 38.3
  TOP w0.119: v1(98.25,60.14) 98.65,60.54 U9.A15
  L7-SIGNAL w0.076: v1(105.79,29.96) 106.04,29.71 106.3,29.71 106.43,29.83 106.43,30.19 104.68,31.94 104.68,36.41 98.96,42.13 98.96,51.77 arc(98.96,51.79) 98.94,51.82 98.94,51.82 arc(98.88,51.91) 98.86,52.02 98.86,60.35 arc(98.86,60.38) 98.86,60.42 98.86,60.42 arc(98.83,60.48) 98.78,60.5 98.74,60.5 arc(98.61,60.47) 98.51,60.4 v1(98.25,60.14)
  BOTTOM w0.119: U3019.52 106.34,28.32 106.22,28.44 106.22,29.54 v1(105.79,29.96)
DSI0_TXCLK_N: length 42.5
  TOP w0.119: U9.E10 v1(103.05,63.35)
  L7-SIGNAL w0.076: v1(103.05,63.35) 102.75,63.05 102.75,62.94 102.79,62.9 103.2,62.9 103.41,62.69 103.41,62.28 103.59,62.1 104,62.1 104.21,61.89 104.21,61.48 104.39,61.3 104.8,61.3 105.01,61.09 105.01,60.53 105.03,60.5 105.03,59.79 104.77,59.53 104.77,49.3 105.36,48.72 105.36,42.87 110.95,37.29 110.95,32.32 109.86,31.23 109.86,30.9 109.93,30.82 110.21,30.82 v1(110.49,31.1)
  BOTTOM w0.119: v1(110.49,31.1) 110.23,31.1 109.95,30.82 109.95,28.44 109.83,28.32 U3019.59
DSI0_TXCLK_P: length 41.4
  TOP w0.119: U9.E11 v1(102.25,63.35)
  L7-SIGNAL w0.076: v1(102.25,63.35) 102.55,63.05 102.55,62.85 102.7,62.71 102.7,62.4 102.91,62.19 103.22,62.19 103.5,61.91 103.5,61.6 103.71,61.39 104.02,61.39 104.3,61.11 104.3,59.76 104.57,59.49 104.57,49.22 105.16,48.63 105.16,42.79 110.74,37.2 110.74,32.41 109.65,31.32 109.65,30.81 109.85,30.62 110.21,30.62 v1(110.49,30.34)
  BOTTOM w0.119: v1(110.49,30.34) 110.22,30.34 110.22,28.44 110.34,28.32 U3019.60
DSI_CL: length 6.4
  TOP w0.229: U3011.13 95.54,33.95 94.13,35.36 R3059.1
DSI_DIAG_EN: length 8.4
  TOP w0.229: U3011.12 96.19,33.05 96.14,33.09 96.14,35.3 94.58,36.85 R3058.1
DSI_TX_CALIB: length 0.6
  TOP w0.229: U9.F12 v1(101.45,64.15)
DSI_UB981_INTB: length 62.6
  TOP w0.191: v1(107.05,74.55) 106.65,74.15 U9.V5
  TOP w0.229: 116.39,21.95 v1(116.32,21.95) 114.71,21.95 112.69,23.96 112.69,25.6 111.38,26.91 107.44,26.91 104.32,23.79 104.32,18.19 106.38,16.13 106.38,15.27 107.16,14.48 v1(107.18,14.48)
  L9-SIGNAL w0.097: 116.97,46.6 107.42,56.15 107.42,61.1 107.21,61.31 106.97,61.31 106.62,61.66 106.62,71.5 106.4,71.71 106.33,71.71 106.26,71.78 106.1,71.78 105.89,72 105.89,72.16 105.89,72.16 105.89,73.9 106.1,74.11 106.48,74.11 106.92,74.55 v1(107.05,74.55)
  BOTTOM w0.229: R3115.2 v1(107.18,14.48) ; R3105.2 v1(116.32,21.95)
EN_3V3IO_LDSW: length 3.7
  TOP w0.127: Q13.G v1(55.32,60.87)
  TOP w0.229: v1(160.15,110.35) 160.17,110.33 R46.2 159.59,109.64 159.41,109.82 U6.3 ; U29.53 v1(78.2,103.14)
EN_DDR0V6_BUCK: length 0.7
  TOP w0.229: U29.46 v1(74.7,103.14)
EN_DRV_OUT: length 46
  TOP w0.229: U27.29 v1(128.07,92.24)
  L2-SIGNAL w0.097: v1(132.97,78.86) 131.95,79.87 131.95,81.52 128.91,84.57 128.91,91.41 v1(128.07,92.24)
  L9-SIGNAL w0.097: TPX279.1 156.84,73.65 141.86,73.65 136.65,78.86 v1(132.97,78.86)
EN_MCU3V3_LDSW: length 2.5
  BOTTOM w0.229: U22.3 63.83,104.06 63.3,104.59 R515.2 ; R277.1 134.62,94.22 v1(134.59,94.22)
ENET_EN: length 1.7
  TOP w0.127: v2(46.35,45.46) 46.25,45.35 U2011.7
  BOTTOM w0.127: R2114.1 46.35,44.95 v2(46.35,45.46)
ENET_EXP_INTB: length 34.2
  TOP w0.229: U9.R28 87.86,71.35 v1(87.85,71.35)
  BOTTOM w0.127: v1(87.85,71.35) 87.44,70.94 83.52,70.94 82.17,69.59 62.1,69.59 61.59,70.09 59.31,70.09 58.67,70.73 TPX164.1
ENET_INH: length 2.3
  TOP w0.127: v2(43.56,44.69) 43.56,44.06 43.85,43.77 U2011.10
  BOTTOM w0.127: v2(43.56,44.69) R2112.1
ENET_INTSN: length 1
  BOTTOM w0.127: R2115.1 R2116.1
ENET_WAKE: length 2.7
  TOP w0.127: U2011.8 45.75,45.68 v2(45.47,45.96)
  BOTTOM w0.127: v2(45.47,45.96) R2113.1
EXT_TDI: length 8.2
  TOP w0.229: U131.2 54.61,50.92 54.1,51.42 54.1,54.98 54.36,55.23 54.36,55.87 54.17,56.06 53.68,56.06 53.65,56.1 J1011.5
EXT_TDO: length 2.2
  TOP w0.229: U130.4 v1(55.4,57.24) ; J1011.4 v1(48.12,55.6)
EXT_TMS: length 1.4
  TOP w0.229: J1011.2 v1(46.54,54.54) ; U129.2 54.83,53.46 v1(54.61,53.67)
FB: length 7.5
  TOP w0.203: v2(178.94,49.52) R1035.1 ; U1008.11 176.01,50.29 176.4,49.9 v2(176.4,49.52) R1041.2
  BOTTOM w0.203: v2(176.4,49.52) v2(178.94,49.52)
FB_5141: length 3.7
  TOP w0.203: R1024.1 R1025.2 195.96,98.8 194.67,100.09 U1007.19
FPD_DOUT0_N: length 6
  BOTTOM w0.119: J3005.3 108.35,5.69 109.3,5.69 109.42,5.82 109.42,8.54 108.85,9.11 108.85,9.52 109.12,9.79 FL3030.3
FPD_DOUT0_P: length 4
  BOTTOM w0.119: FL3030.2 108.31,9.79 108.58,9.51 108.58,9.13 108.43,8.98 107.29,8.98 J3005.1
G720_VDDIO: length 2.7
  TOP w0.229: U2011.34 52.05,42.77 52.58,43.3
GPIO0_6: length 50.4
  TOP w0.191: U9.AD20 94.65,78.95 v1(94.25,79.35)
  L9-SIGNAL w0.097: TPX323.1 53.09,90.79 58.04,90.79 58.42,90.41
  L9-SIGNAL w0.102: 58.42,90.41 87.5,90.41 88.39,89.52 88.39,87.75 90.22,85.92 91.1,85.92 91.43,85.58 91.43,85.19 93.02,83.6 93.02,80.81 93.25,80.58 93.6,80.58 93.85,80.33 93.85,79.75 94.08,79.52 94.08,79.51 v1(94.25,79.35)
GPIO0_61: length 34
  TOP w0.191: v1(87.05,77.75) 87.45,77.35 U9.AB29
  L5-PWR/GND w0.097: v1(87.05,77.75) 86.65,77.75 86.33,77.43 55.4,77.43 55.24,77.59 TPX59.1
GPIO0_78/PRG0_RGMII2_TX_CTL: length 34.1
  TOP w0.191: v1(87.05,80.95) 87.45,80.55 U9.AF29
  L7-SIGNAL w0.097: TPX32.1 59.56,81.4 60.2,80.76 86.48,80.76 86.67,80.95 v1(87.05,80.95)
GPIO0_79/PRG0_RGMII2_TXC: length 37.2
  TOP w0.191: U9.AG29 87.45,81.35 v1(87.05,81.75)
  L7-SIGNAL w0.097: v1(87.05,81.75) 85.98,81.75 84.93,82.79 56.52,82.79 55.88,82.16 51.82,82.16 TPX56.1
GPIO0_127/EQEP0_S/MLB0_MLBCLK: length 48.5
  TOP w0.191: v1(107.85,78.55) 107.85,78.54 U9.AC4
  L5-PWR/GND w0.097: v1(107.85,78.55) 108.24,78.93 110.44,78.93 111.63,80.13 120.35,80.13 121.87,81.64 138.82,81.64 142.75,77.71 150.88,77.71 TPX204.1
GPIO1_0/EQEP0_I/MLB0_MLBDAT: length 37.7
  TOP w0.191: v1(107.05,79.35) 107.05,79.34 U9.AD5
  L9-SIGNAL w0.102: v1(107.05,79.35) 106.82,79.58 106.82,79.59 106.69,79.72 106.69,79.99 106.68,80 106.68,80.3 106.69,80.31 106.69,80.79 106.68,80.8 106.68,81.1 106.69,81.11 106.69,81.59 106.68,81.6 106.68,81.9 106.69,81.91 106.69,82.4 106.68,82.4 106.68,83.61 107.62,84.55 107.62,86.88 108.58,87.85 108.58,89.94 110.19,91.54 110.19,111.06 TPX243.1
GPIO1_11/MAIN_I3C0_SDAPULLEN: length 56.1
  TOP w0.191: v1(109.45,73.75) 109.05,73.35 U9.U2
  L7-SIGNAL w0.097: TPX256.1 159.89,71.87 142.62,71.87 137.03,77.46 119.89,77.46 118.36,75.94 114.68,75.94 112.28,73.54 110.56,73.54 110.41,73.38 109.82,73.38 v1(109.45,73.75)
GPIO1_12/MLB0_REFCLK: length 53
  TOP w0.191: v1(108.65,73.75) 108.65,73.74 U9.U3
  L9-SIGNAL w0.097: TPX229.1 155.06,72.9 151.48,72.9 151.47,72.89 141.86,72.89 137.37,77.37 116.37,77.37 112.37,73.37 109.03,73.37 v1(108.65,73.75)
GPIO1_23/UART9_RXD: length 47.4
  TOP w0.229: U9.T28 88.25,72.55 v1(87.85,72.15)
  BOTTOM w0.127: TPX188.1 43.81,73.9 69.47,73.9 72,71.38 80.4,71.38 81.34,72.31 86.65,72.31 86.88,72.54 87.45,72.54 v1(87.85,72.15)
GPIO1_24/UART9_TXD: length 51.7
  TOP w0.229: v1(87.05,72.15) 87.45,72.55 U9.T29
  L5-PWR/GND w0.097: v1(87.05,72.15) 81.56,72.15 80.69,71.28 71.49,71.28 70.31,70.09 62.86,70.09 59.9,67.13 58.84,67.13 57.15,65.44 57.15,58.41 56.64,57.9 56.64,54.69 56.09,54.14 56.09,50.62 TPX113.1
GPIO_MCU_RGMII1_RST#: length 52.4
  TOP w0.229: U9.F27 88.65,64.15 v1(88.65,64.15)
  L4-SIGNAL w0.097: v1(88.65,64.15) 88.21,63.71 88.21,63.19 88,62.98 87.77,62.98 87.41,62.63 87.41,62.39 87.2,62.18 84.29,62.18 83.57,61.46 81.28,61.46 80.64,62.09 79.12,62.09 78.87,61.84 60.71,61.84 59.56,60.7 56.1,60.7 55.49,61.31 55.46,61.31 55.31,61.46 44.83,61.46 44.32,61.97 40.54,61.97 40.28,61.71 TPX17.1
H_DDR_RET_1V1: length 30
  TOP w0.191: U9.P6 v1(106.25,70.55)
  TOP w0.229: U29.47 75.2,101.82 v1(75.39,101.64)
  L9-SIGNAL w0.097: 109.89,82.46 109.61,82.18 109.37,82.18 109.09,81.9 109.09,81.67 108.8,81.38 108.57,81.38 108.29,81.1 108.29,80.87 108,80.58 107.77,80.58 107.49,80.3 107.49,80 107.49,80 107.49,76.87 107.2,76.58 106.97,76.58 106.69,76.3 106.69,76.07 106.4,75.78 106.17,75.78 105.89,75.5 105.89,75.27 105.6,74.98 105.37,74.98 105.09,74.7 105.09,72 105.3,71.78 105.54,71.78 105.89,71.43 105.89,70.91 v1(106.25,70.55)
  L9-SIGNAL w0.102: 109.89,82.46 109.89,82.7 109.89,82.71 109.89,82.75 114.38,87.24 118.7,87.24 v1(119.84,88.38)
  BOTTOM w0.229: R180.2 v1(119.84,88.38)
H_I3C0_SCL: length 46.4
  TOP w0.191: U9.W2 109.45,75.34 v1(109.45,75.35)
  L9-SIGNAL w0.097: v1(109.45,75.35) 109.88,74.92 112.9,74.92 117.6,79.62 136.27,79.62 140.97,74.92 150.5,74.92 TPX255.1
H_I3C0_SDA: length 46.8
  TOP w0.191: v1(110.25,75.35) 110.25,75.34 U9.W1
  L9-SIGNAL w0.097: v1(110.25,75.35) 112.74,75.35 117.31,79.92 136.48,79.92 141.22,75.17 151.51,75.17 TPX301.1
H_MCU_INT#: length 39.3
  TOP w0.229: v1(81.64,109.82) 81.48,109.67 U29.14 ; U27.14 128.07,102.43 v1(127.91,102.58) ; R93.2 81.34,63.38 81.64,63.08 82.73,63.08 83.01,62.8 v1(83.01,62.22)
  L5-PWR/GND w0.097: 73.3,110.63 80.82,110.63 v1(81.64,109.82) ; v1(83.01,62.22) 79.83,59.04 61.09,59.04 v1(60.58,58.54)
  BOTTOM w0.229: R273.1 127.85,102.64 v1(127.91,102.58)
H_MCU_PORZ: length 0.7
  TOP w0.229: U27.25 v1(128.05,95.65)
H_MDIO_D: length 0.7
  BOTTOM w0.127: v1(50.13,48.73) 50.16,48.7 R2111.2
H_SOC_PORZ: length 0.7
  TOP w0.229: U27.53 v1(134.59,99.15)
H_WKUP_LFOSC0_XI: length 2.7
  TOP w0.229: R504.1 R3145.1 R3146.2
  BOTTOM w0.229: v1(84.71,69.59) 84.67,69.55 R281.2
HDRV1_N: length 20.3
  TOP w0.305: U1008.28 168.66,58.03 C1049.2 166.75,59.17 166.12,59.81 v2(166.12,62.47)
  BOTTOM w0.305: v2(166.12,62.47) 166.75,63.11 166.75,70.35 v2(170.56,74.16)
  vias: v2(168.78,85.33) v2(168.78,84.44) v2(168.78,83.56) v2(168.78,82.67) v2(168.78,81.78) v2(168.78,80.89) v2(168.78,80) v2(168.78,79.11) v2(168.78,78.22) v2(168.78,77.33) v2(168.78,76.44) v2(168.78,75.55) v2(169.67,85.33) v2(169.67,84.44) v2(169.67,83.56) v2(169.67,82.67) v2(169.67,81.78) v2(169.67,80.89) v2(169.67,80) v2(169.67,79.11) v2(169.67,78.22) v2(169.67,77.33) v2(169.67,76.44) v2(169.67,75.55) v2(172.09,76.06) v2(172.97,76.06) v2(173.86,76.06) v2(174.75,76.06)
HDRV1_P: length 22.5
  TOP w0.305: R1014.2 v2(164.47,75.3) ; U1008.27 170.16,59.19 v2(169.42,59.93)
  BOTTOM w0.305: v2(164.47,75.3) 163.7,74.54 163.7,63.36 167.13,59.93 v2(169.42,59.93)
HDRV2_N: length 17.7
  TOP w0.305: U1008.18 176.01,59.16 176.53,59.68 C1046.1 177.24,61.41 D1006.1 177.24,64.99 D1003.2 v2(178.63,65.01)
  L2-SIGNAL w0.305: v2(178.63,65.01) 179.8,66.19 179.8,72.79 v2(179.45,73.14)
  vias: v2(176.28,76.06) v2(177.16,76.06) v2(178.05,76.06) v2(179.45,85.84) v2(179.45,84.95) v2(179.45,84.06) v2(179.45,83.17) v2(179.45,82.29) v2(179.45,81.4) v2(179.45,80.51) v2(179.45,79.62) v2(179.45,78.73) v2(179.45,77.84) v2(179.45,76.95) v2(179.45,76.06) v2(179.45,75.17) v2(180.34,85.84) v2(180.34,84.95) v2(180.34,84.06) v2(180.34,83.17) v2(180.34,82.29) v2(180.34,81.4) v2(180.34,80.51) v2(180.34,79.62) v2(180.34,78.73) v2(180.34,77.84) v2(180.34,76.95) v2(180.34,76.06)
HDRV2_P: length 23.1
  TOP w0.305: R1015.1 v2(187.77,74.41) ; U1008.19 175.36,59.4 v2(175.77,59.81)
  BOTTOM w0.305: v2(187.77,74.41) 186.44,74.41 183.9,71.87 183.9,69.2 176.53,61.84 176.53,60.57 v2(175.77,59.81)
I2C0_SCL: length 42.5
  TOP w0.191: U9.AC5 106.65,78.15 v1(107.05,78.55)
  TOP w0.229: R20.2 TPX265.1
  L9-SIGNAL w0.102: TPX265.1 113.41,114.29 112.65,114.29 109.89,111.53 109.89,91.72 108.18,90.01 108.18,87.92 107.31,87.06 107.31,84.98 105.89,83.55 105.89,83.51 105.88,83.5 105.88,80 106.1,79.78 106.34,79.78 106.62,79.5 106.62,79.17 106.92,78.87 v1(107.05,78.55)
I2C0_SDA: length 40.4
  TOP w0.191: v1(107.05,76.95) 107.05,76.94 U9.AA5
  TOP w0.229: R23.2 TPX291.1
  L7-SIGNAL w0.097: TPX291.1 141.99,81.52 111.49,81.52 110.64,80.68 110.54,80.68 110.38,80.52 110.1,80.52 109.89,80.3 109.89,80.02 109.58,79.72 109.3,79.72 109.09,79.5 109.09,79.22 108.81,78.94 108.53,78.94 108.22,78.64 108.22,78.4 108.01,78.18 107.76,78.18 107.46,77.88 107.46,77.36 v1(107.05,76.95)
I2C1_SCL: length 63.6
  TOP w0.191: v1(106.25,76.15) 105.85,75.75 U9.Y6
  TOP w0.229: v1(103.25,26.31) 103.71,26.31 103.75,26.28 R37.2
  L9-SIGNAL w0.097: v1(103.25,26.31) 104.02,27.08 106.72,27.08 107.82,28.18 107.82,33.01 108.97,34.15 108.97,42.66 100.73,50.9 100.73,59.44 100.74,59.46 100.74,59.76 100.77,59.78 100.8,59.78 101.02,59.99 101.02,71.67 101.13,71.78 101.6,71.78 101.82,71.99 101.82,72.47 102.73,73.38 103.2,73.38 103.42,73.6 103.42,74.07 103.53,74.18 104,74.18 104.22,74.4 104.22,74.87 104.33,74.98 104.8,74.98 105.02,75.2 105.02,75.67 105.13,75.78 105.89,75.78 v1(106.25,76.15)
  BOTTOM w0.229: v1(103.25,26.31) 103.45,26.52 U3019.47
I2C1_SDA: length 63.6
  TOP w0.191: U9.AA6 106.25,76.94 v1(106.25,76.95)
  TOP w0.229: R38.2 103.81,27.29 103.71,27.2 v1(103.25,27.2)
  L9-SIGNAL w0.097: v1(103.25,27.2) 103.64,27.2 103.73,27.29 106.49,27.29 107.38,28.18 107.38,33.19 108.52,34.34 108.52,42.6 100.52,50.6 100.52,59.49 100.22,59.79 100.22,72.22 101.38,73.38 101.6,73.38 101.82,73.6 101.82,73.83 102.1,74.11 102.34,74.11 102.62,74.4 102.62,74.63 102.9,74.92 103.14,74.92 103.42,75.2 103.42,75.43 103.7,75.72 103.94,75.72 104.22,76 104.22,76.23 104.5,76.52 105.82,76.52 v1(106.25,76.95)
  BOTTOM w0.229: U3019.48 103.44,27.02 v1(103.25,27.2)
I2C3_SCL: length 49.2
  TOP w0.229: R81.2 TPX112.1 ; U9.T26 89.46,72.15 v1(89.45,72.15)
  BOTTOM w0.127: v1(89.45,72.15) 88.46,73.14 80.52,73.14 79.88,72.51 76.71,72.51 76.33,72.89 71.37,72.89 69.85,74.41 TPX112.1
I2C3_SDA: length 50.4
  TOP w0.229: U9.T25 90.65,72.55 v1(90.25,72.15) ; R79.2 TPX163.1
  BOTTOM w0.127: TPX163.1 43.69,71.24 58.67,71.24 59.56,70.35 61.72,70.35 62.24,69.83 81.9,69.83 83.82,71.74 89.84,71.74 v1(90.25,72.15)
I2C6_SCL: length 44.7
  TOP w0.191: U9.AA3 108.25,76.55 v1(108.65,76.95)
  TOP w0.229: R27.2 TPX292.1
  L7-SIGNAL w0.097: TPX292.1 146.94,75.94 146.1,75.94 146.09,75.93 145.76,75.93 145.75,75.94 144.83,75.94 144.82,75.93 144.49,75.93 144.48,75.94 141.86,75.94 138.09,79.7 119.84,79.7 117.86,77.71 113.69,77.71 113.32,77.34 109.05,77.34 v1(108.65,76.95)
I2C6_SDA: length 50.6
  TOP w0.191: v1(109.45,76.15) 109.45,76.14 U9.Y2
  TOP w0.229: R66.2 TPX460.1
  L5-PWR/GND w0.097: v1(109.45,76.15) 109.9,76.59 110.89,76.59 111.51,77.21 116.33,77.21 117.82,78.7 120.7,78.7 121.79,79.79 137.41,79.79 142.28,74.92 154.31,74.92 TPX460.1
LDRV1: length 13.6
  TOP w0.305: v2(177.67,67.11) 177.67,67.93 ; v2(171.96,60.44) 171.46,59.94 U1008.25
  BOTTOM w0.305: v2(177.67,67.11) 174.94,64.38 172.97,64.38 171.96,63.36 v2(171.96,60.44)
LDRV2: length 11.9
  TOP w0.305: 178.94,67.93 v2(178.94,67.05) ; U1008.21 v2(174.06,60.13)
  BOTTOM w0.305: v2(178.94,67.05) 174.06,62.16 v2(174.06,60.13)
LEOA_GPIO3: length 1.7
  TOP w0.229: U27.46 v1(134.59,95.65)
  BOTTOM w0.229: R276.2 R277.2
LEOA_GPIO8: length 10.9
  TOP w0.229: v1(133.1,85.33) 132.97,85.21 R504.2 ; v1(133.87,94.22) 134.07,94.03 U27.41
  L2-SIGNAL w0.097: v1(133.87,94.22) 133.87,92.93 134.03,92.78 134.03,90.08 133.1,89.14 v1(133.1,85.33)
LEOA_GPIO9: length 1.6
  TOP w0.229: U27.19 127.9,98.65 v1(128.05,98.8)
  BOTTOM w0.229: R522.2 127.98,98.83 128.02,98.8 v1(128.05,98.8)
LEOA_GPIO10: length 8.9
  TOP w0.229: v1(134.57,92.67) U27.42 ; v1(134.35,85.34) 134.35,85.35 134.51,85.5 R502.2
  L4-SIGNAL w0.097: v1(134.57,92.67) 134.57,92.26 134.47,92.17 134.47,86.33 134.35,86.21 v1(134.35,85.34)
LEOA_OSC32KCAP: length 1.6
  TOP w0.229: v1(133.65,92.62) 133.57,92.7 U27.40
  BOTTOM w0.229: C505.1 133.65,92.83 v1(133.65,92.62)
LEOA_OSC32KIN: length 9
  TOP w0.229: v1(132.59,91.94) 132.59,92.74 132.57,92.76 132.57,92.99 132.57,93 132.57,93.01 132.57,93.05 132.57,93.06 132.57,93.06 U27.38
  BOTTOM w0.229: v1(132.59,91.94) 132.72,91.81 133.98,91.81 136.57,89.23 Y6.2 136.57,87.63 136.32,87.38 C503.2
LEOA_OSC32KOUT: length 11.4
  TOP w0.229: v1(133.1,92.32) 133.07,92.35 U27.39
  BOTTOM w0.229: v1(133.1,92.32) 133.24,92.17 137.05,92.17 139.06,90.16 139.06,90.02 139.07,90.01 Y6.1 139.07,87.71 139.4,87.38 C506.2
LEOA_SCLK: length 1.5
  TOP w0.229: U27.23 v1(128.05,96.65) ; U29.23 v1(75.7,109.69)
LEOA_SDATA: length 1.7
  TOP w0.229: U27.24 v1(126.47,96.15) ; U29.24 v1(75.2,111.27)
LEOB_GPIO1: length 16.3
  TOP w0.229: R287.2 v1(56.77,108.19) ; v1(71.73,108.17) U29.32
  L9-SIGNAL w0.097: v1(71.73,108.17) 57.19,108.17 57.16,108.19 v1(56.77,108.19)
LEOB_GPIO1_RES: length 1.7
  TOP w0.229: TP108.1 R287.1
LEOB_GPIO2: length 18.5
  TOP w0.229: v1(73.18,107.67) U29.33 ; R288.2 v1(56.89,105.66)
  L9-SIGNAL w0.097: v1(56.89,105.66) 58.9,107.67 v1(73.18,107.67)
LEOB_GPIO2_RES: length 1.8
  TOP w0.229: R288.1 54.91,105.66 54.91,105.65 TP109.1
LEOB_GPIO7: length 14
  TOP w0.229: v1(78.1,111.24) 78.2,111.14 U29.18 ; R494.2 v1(78.61,122.93)
  L9-SIGNAL w0.097: v1(78.61,122.93) 78.61,119.5 79.38,118.73 79.38,114.92 78.41,113.96 78.41,112.06 78.1,111.75 v1(78.1,111.24)
LEOB_GPIO7_RES: length 1.8
  TOP w0.229: R494.1 78.61,125.59 TP3016.1
LEOB_GPIO8: length 19
  TOP w0.229: v1(73.18,103.67) U29.41 ; R495.2 v1(56.9,102.99)
  L9-SIGNAL w0.097: v1(73.18,103.67) 72.79,103.67 72.74,103.62 70.87,103.62 69.22,101.97 65.53,101.97 64.52,102.99 v1(56.9,102.99)
LEOB_GPIO8_RES: length 1.7
  TOP w0.229: TP3017.1 R495.1
LEOB_GPIO9: length 16.1
  TOP w0.229: v1(78,109.67) 77.7,109.97 U29.19 ; R496.2 v1(77.34,122.93)
  L9-SIGNAL w0.097: v1(78,109.67) 78,110.33 77.73,110.6 77.73,111.88 78.1,112.26 78.1,114.16 78.99,115.05 78.99,118.61 78.36,119.24 78.36,121.91 v1(77.34,122.93)
LEOB_GPIO9_RES: length 1.8
  TOP w0.229: R496.1 77.34,125.47 TP3018.1
LEOB_GPIO10: length 17.5
  TOP w0.229: R503.1 v1(56.77,100.57) ; v1(71.37,103.17) U29.42
  L9-SIGNAL w0.097: v1(71.37,103.17) 69.97,101.76 57.96,101.76 v1(56.77,100.57)
LEOB_GPIO10_RES: length 1.7
  TOP w0.229: TP115.1 R503.2
LFDSI: length 2
  TOP w0.229: C3056.1 v1(104.14,28.35)
  BOTTOM w0.229: U3019.49 104.83,28.03 104.52,28.35 v1(104.14,28.35)
LFT: length 2.3
  BOTTOM w0.229: C3114.1 110.36,17.17 110.87,17.68 110.87,18.73 U3019.20
LPDDR4_CA0: length 33.6
  TOP w0.33: v1(130.93,68.41) 130.53,68.73 U11.R2 ; U11.H2 v1(130.93,64.51) ; U9.G4 v1(107.85,64.95)
  L2-SIGNAL w0.142: v1(130.93,68.41) 130.53,68.01 130.53,67.59 130.25,67.31 130.25,66.83 v1(130.52,66.56) 130.52,65.16 130.52,64.88 130.89,64.51 v1(130.93,64.51)
  L7-SIGNAL w0.163: v1(130.52,66.56) 129.71,65.75 128.32,65.75 127.2,64.63 127.2,63.64 127.46,63.39 127.46,63.01 127.1,62.65 126.7,62.65 126.31,63.04 122.02,63.04 121.94,62.96 120.88,62.96 120.24,62.32 112.17,62.32 111.1,63.39 111.1,64.07 110.63,64.55 108.25,64.55 v1(107.85,64.95)
LPDDR4_CA1: length 33.7
  TOP w0.33: U9.H3 v1(108.65,65.75) ; v1(130.13,68.41) 130.53,68.08 U11.P2 ; U11.J2 v1(130.13,64.51)
  L2-SIGNAL w0.142: v1(130.13,64.51) 129.87,64.77 129.81,64.77 129.73,64.84 v1(129.73,66.56) 129.45,66.85 129.45,67.31 129.73,67.6 129.73,68.02 v1(130.13,68.41)
  L7-SIGNAL w0.163: v1(129.73,66.56) 129.84,66.67 129.84,67.1 129.64,67.3 128.09,67.3 127.43,66.64 127.13,66.64 126.93,66.44 126.93,66.15 127.07,66 127.17,66 127.37,65.8 127.37,65.51 126.67,64.81 126.67,63.72 126.42,63.46 126.32,63.46 126.3,63.44 121.96,63.44 121.94,63.46 120.65,63.46 120.02,62.83 112.5,62.83 111.68,63.64 111.68,64.94 111.43,65.19 110.57,65.19 110.42,65.35 109.05,65.35 v1(108.65,65.75)
LPDDR4_CA2: length 33.7
  TOP w0.33: U9.K5 v1(107.05,67.35) ; U11.R9 124.93,68.73 v1(124.53,68.41) ; U11.H9 v1(124.53,64.51)
  L2-SIGNAL w0.142: v1(124.53,64.51) 124.79,64.77 124.85,64.77 124.92,64.84 v1(124.92,66.56) 125.2,66.84 125.2,67.22 124.93,67.49 124.93,68 v1(124.53,68.41)
  L7-SIGNAL w0.163: v1(124.92,66.56) 125.33,66.97 126.47,66.97 127.02,67.52 127.02,69.42 126.54,69.89 122.13,69.89 122.1,69.92 121.18,69.92 119.76,71.34 117.32,71.34 116.74,70.76 116.74,70.41 116.4,70.07 111.38,70.07 110.66,69.35 109.29,69.35 109.05,69.11 109.05,68.78 108.82,68.55 107.63,68.55 107.45,68.37 107.45,67.75 v1(107.05,67.35)
LPDDR4_CA3: length 33.6
  TOP w0.33: v1(123.73,68.41) 124.13,68.73 U11.R10 ; v1(107.85,66.55) 107.45,66.95 U9.J4 ; U11.H10 v1(123.73,64.51)
  L2-SIGNAL w0.142: v1(123.73,68.41) 124.13,68.01 124.13,67.53 124.41,67.25 124.41,66.83 v1(124.13,66.56) 124.13,64.87 123.79,64.52 v1(123.73,64.51)
  L7-SIGNAL w0.163: v1(124.13,66.56) 124.13,67.05 124.43,67.35 126.23,67.35 126.66,67.77 126.66,69.16 126.35,69.47 121.96,69.47 121.61,69.13 120.4,69.13 119.94,69.59 119.94,70.37 119.68,70.63 117.69,70.63 117.49,70.42 117.49,69.7 117.33,69.54 111.7,69.54 110.71,68.54 110.42,68.54 110.42,68.55 110.03,68.55 109.85,68.37 109.85,67.98 109.62,67.75 108.47,67.75 108.25,67.53 108.25,66.95 v1(107.85,66.55)
LPDDR4_CA4: length 33.6
  TOP w0.33: U11.R11 123.33,68.73 v1(122.93,68.41) ; U9.K2 v1(109.45,67.35) ; U11.H11 v1(122.93,64.51)
  L2-SIGNAL w0.142: v1(122.93,64.51) 123.34,64.92 123.34,65.34 123.36,65.36 123.36,66.09 123.32,66.12 v1(123.32,66.56) 123.6,66.83 123.6,67.25 123.34,67.51 123.34,68 v1(122.93,68.41)
  L7-SIGNAL w0.163: v1(123.32,66.56) 123.71,66.95 123.71,67.22 123.59,67.35 123.26,67.35 123.03,67.12 121.72,67.12 121.51,67.33 121.51,68.21 121.18,68.54 120.56,68.54 120.41,68.39 119.48,68.39 119.25,68.62 119.25,69 119.05,69.2 118.36,69.2 118.16,69 118.16,67.71 117.96,67.5 117.07,67.5 116.81,67.76 116.81,68.8 116.61,69 116.03,69 115.82,68.8 115.82,67.71 115.62,67.5 114.86,67.5 114.71,67.66 114.71,68.87 114.55,69.03 114.07,69.03 113.91,68.87 113.91,67.66 113.75,67.5 113.53,67.5 113.37,67.66 113.37,68.54 113.21,68.7 112.98,68.7 112.82,68.54 112.82,67.66 112.66,67.5 112.44,67.5 112.28,67.66 112.28,68.54 112.12,68.7 111.73,68.7 111.61,68.57 111.61,67.93 111.42,67.75 110.09,67.75 110.07,67.73 110.06,67.73 109.67,67.35 v1(109.45,67.35)
LPDDR4_CA5: length 33.6
  TOP w0.33: U11.J11 v1(122.93,65.16) ; U9.H5 v1(107.05,65.75) ; v1(122.93,67.76) 123.33,68.08 U11.P11
  L2-SIGNAL w0.142: v1(122.93,67.76) 123.09,67.6 123.09,67.14 122.97,67.02 122.09,67.02 121.95,66.88 v1(121.95,66.56) 122.34,66.17 122.89,66.17 123.06,66 123.06,65.66 122.93,65.52 v1(122.93,65.16)
  L7-SIGNAL w0.163: v1(121.95,66.56) 121.39,66.56 121.11,66.28 120.75,66.28 120.52,66.51 120.52,67.72 120.36,67.88 119.97,67.88 119.81,67.72 119.81,66.06 119.61,65.85 119.34,65.85 119.18,66.01 119.18,66.68 119.02,66.84 118.61,66.84 118.45,66.68 118.45,66.21 118.29,66.05 118.06,66.05 117.9,66.21 117.9,66.68 117.74,66.84 117.51,66.84 117.35,66.68 117.35,66.07 117.19,65.91 116.97,65.91 116.81,66.07 116.81,66.94 116.65,67.1 116.42,67.1 116.26,66.94 116.26,66.07 116.1,65.91 115.88,65.91 115.72,66.07 115.72,66.68 115.56,66.84 115.33,66.84 115.17,66.68 115.17,66.07 115.01,65.91 114.78,65.91 114.62,66.07 114.62,66.72 114.42,66.92 114.05,66.92 113.84,66.72 113.84,66.13 113.64,65.93 113.33,65.93 113.13,66.13 113.13,66.74 112.91,66.96 110.43,66.96 110.42,66.95 109.25,66.95 109.05,66.75 109.05,66.35 108.85,66.15 107.45,66.15 v1(107.05,65.75)
LPDDR4_CK_C: length 33.6
  TOP w0.229: U11.P9 124.93,68.08 v1(125.33,68.41) ; U9.J1 109.92,66.94 110.25,66.61 v1(110.25,66.55) ; U11.J9 v1(125.33,64.51)
  L2-SIGNAL w0.14: v1(125.33,64.51) 125.74,64.92 125.74,66.52 v1(125.7,66.56) 125.7,66.92 125.98,67.2 125.98,67.75 v1(125.33,68.41)
  L7-SIGNAL w0.163: v1(110.25,66.55) 110.25,66.32 110.42,66.16 110.58,66.16 110.67,66.08 112.22,66.08 112.57,65.72 112.57,63.95 112.72,63.8 113.16,63.8 113.39,64.02 113.39,64.89 113.79,65.29 114.35,65.29 114.73,64.91 114.73,63.85 114.86,63.72 115.37,63.72 115.54,63.89 115.54,64.85 115.92,65.22 116.45,65.22 116.79,64.89 116.79,63.84 116.92,63.71 117.29,63.71 117.53,63.95 117.53,64.86 117.93,65.27 118.6,65.27 118.92,64.94 118.92,63.93 119.1,63.74 119.48,63.74 119.66,63.92 119.66,64.86 120.02,65.22 120.85,65.22 121.56,65.93 125.78,65.93 126.02,66.17 126.02,66.32 125.78,66.56 v1(125.7,66.56)
